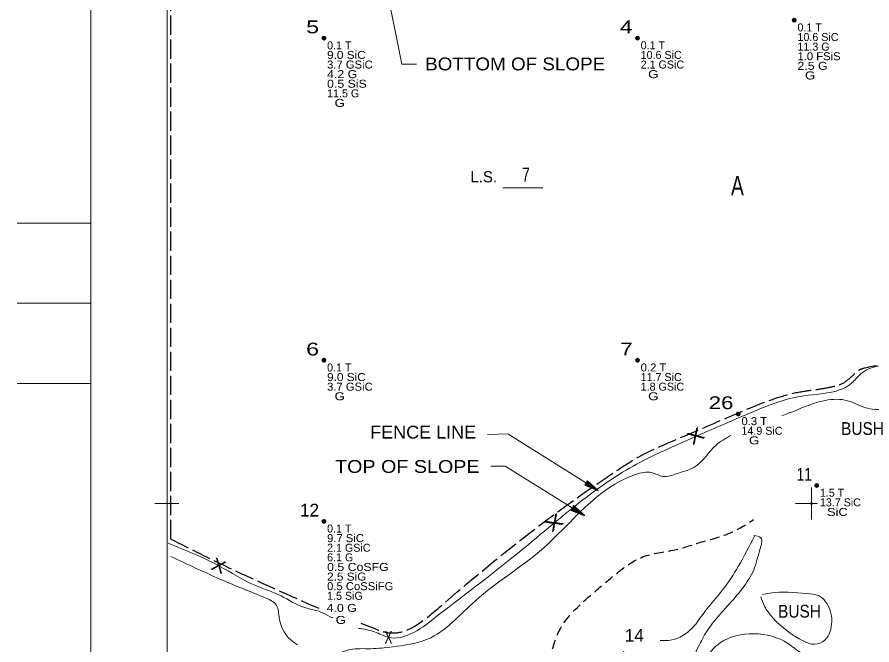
# Model space of a CAD drawing. Extents: x -496 to 480, y -450 to 700.
# Drawn here: x -496 to 38, y -88 to 304 of the extents above; entities that cross this region are included whole.
import ezdxf
from ezdxf.enums import TextEntityAlignment as Align

# ---------------------------------------------------------------- set-up
doc = ezdxf.new("R2010")
doc.units = 0
doc.header["$LTSCALE"] = 2
doc.header["$PDMODE"] = 32
doc.header["$PDSIZE"] = 1
doc.linetypes.add('LONG_DASHED', pattern=[7.5, 6, -1.5])
doc.linetypes.add('MEDIUM_DASHED', pattern=[4.5, 3, -1.5])
for name, color, linetype, lineweight in [('1', 7, 'Continuous', 13), ('2', 7, 'Continuous', 35), ('3', 7, 'Continuous', 13), ('4', 7, 'Continuous', 25)]:
    doc.layers.add(name, color=color, linetype=linetype, lineweight=lineweight)

msp = doc.modelspace()

# ---------------------------------------------------------------- linework, layer by layer
at = {"layer": '1'}
for p, q in [((-402.391, 402.339), (-402.391, -402.333)), ((-192.754, 197.096), (-167.754, 197.096)), ((-450.017, 174.973), (-496.057, 174.973)), ((-450.017, 124.973), (-496.057, 124.973)), ((-450.017, 74.973), (-496.057, 74.973)), ((-0.017, -10.027), (-0.017, 9.973)), ((-395.017, -0.027), (-410.017, -0.027)), ((-10.017, -0.027), (3.779, -0.027))]:
    msp.add_line(p, q, dxfattribs=at)
msp.add_lwpolyline([(449.983, -450.027), (449.983, 399.973), (449.983, 699.973), (-450.017, 699.973), (-450.017, 49.973), (-450.017, -450.027)], dxfattribs=at)
for p in [(0, 0), (0.001, -0.011)]:
    msp.add_point(p, dxfattribs=at)
at = {"layer": '2', "linetype": 'LONG_DASHED', "lineweight": 25}
msp.add_line((-400, -22.268), (-400, 393.12), dxfattribs=at)
at = {"layer": '2'}
for centre in [(-10.765, 301.781), (-304.484, 290.604), (-108.671, 290.604), (-304.484, 89.429), (-108.671, 89.429), (-45.731, 55.9), (3.222, 11.194), (-304.484, -11.159)]:
    msp.add_circle(centre, 1, dxfattribs=at)
for points in [[(-10.775, 302.668), (-10.045, 302.263), (-9.894, 301.415), (-10.579, 300.887), (-11.388, 301.117), (-11.674, 301.876), (-11.427, 302.437), (-10.854, 302.606), (-10.18, 302.112), (-10.197, 301.37), (-10.714, 301.112), (-11.236, 301.28), (-11.461, 301.926), (-10.877, 302.392), (-10.438, 301.859), (-10.478, 301.376), (-11.107, 301.511), (-10.961, 302.145), (-10.669, 301.595)], [(-304.495, 291.491), (-303.765, 291.087), (-303.613, 290.239), (-304.298, 289.711), (-305.107, 289.941), (-305.394, 290.699), (-305.147, 291.261), (-304.574, 291.429), (-303.9, 290.935), (-303.916, 290.194), (-304.433, 289.935), (-304.956, 290.104), (-305.18, 290.75), (-304.596, 291.216), (-304.158, 290.682), (-304.197, 290.199), (-304.826, 290.334), (-304.68, 290.969), (-304.388, 290.418)], [(-108.682, 291.491), (-107.952, 291.087), (-107.8, 290.239), (-108.485, 289.711), (-109.294, 289.941), (-109.581, 290.699), (-109.334, 291.261), (-108.761, 291.429), (-108.087, 290.935), (-108.103, 290.194), (-108.62, 289.935), (-109.143, 290.104), (-109.367, 290.75), (-108.783, 291.216), (-108.345, 290.682), (-108.384, 290.199), (-109.013, 290.334), (-108.867, 290.969), (-108.575, 290.418)], [(-304.495, 90.316), (-303.765, 89.911), (-303.613, 89.063), (-304.298, 88.535), (-305.107, 88.766), (-305.394, 89.524), (-305.147, 90.085), (-304.574, 90.254), (-303.9, 89.76), (-303.916, 89.018), (-304.433, 88.76), (-304.956, 88.928), (-305.18, 89.574), (-304.596, 90.041), (-304.158, 89.507), (-304.197, 89.024), (-304.826, 89.159), (-304.68, 89.793), (-304.388, 89.243)], [(-108.682, 90.316), (-107.952, 89.911), (-107.8, 89.063), (-108.485, 88.535), (-109.294, 88.766), (-109.581, 89.524), (-109.334, 90.085), (-108.761, 90.254), (-108.087, 89.76), (-108.103, 89.018), (-108.62, 88.76), (-109.143, 88.928), (-109.367, 89.574), (-108.783, 90.041), (-108.345, 89.507), (-108.384, 89.024), (-109.013, 89.159), (-108.867, 89.793), (-108.575, 89.243)], [(-45.742, 56.787), (-45.012, 56.382), (-44.86, 55.534), (-45.545, 55.006), (-46.354, 55.236), (-46.641, 55.995), (-46.394, 56.556), (-45.821, 56.725), (-45.147, 56.231), (-45.163, 55.489), (-45.68, 55.231), (-46.203, 55.399), (-46.427, 56.045), (-45.843, 56.511), (-45.405, 55.978), (-45.444, 55.495), (-46.073, 55.63), (-45.927, 56.264), (-45.635, 55.714)], [(3.211, 12.081), (3.941, 11.677), (4.093, 10.828), (3.408, 10.3), (2.599, 10.531), (2.312, 11.289), (2.56, 11.851), (3.133, 12.019), (3.807, 11.525), (3.79, 10.783), (3.273, 10.525), (2.751, 10.694), (2.526, 11.34), (3.11, 11.806), (3.548, 11.272), (3.509, 10.789), (2.88, 10.924), (3.026, 11.559), (3.318, 11.008)], [(-304.495, -10.272), (-303.765, -10.676), (-303.613, -11.524), (-304.298, -12.052), (-305.107, -11.822), (-305.394, -11.064), (-305.147, -10.502), (-304.574, -10.334), (-303.9, -10.828), (-303.916, -11.569), (-304.433, -11.828), (-304.956, -11.659), (-305.18, -11.013), (-304.596, -10.547), (-304.158, -11.081), (-304.197, -11.564), (-304.826, -11.429), (-304.68, -10.794), (-304.388, -11.345)]]:
    msp.add_spline(points, degree=3, dxfattribs=at)
at = {"layer": '2', "linetype": 'LONG_DASHED', "lineweight": 25}
for points in [[(-121.657, 20.504), (-107.33, 29.42), (-86.423, 39.115), (-52.45, 53.658), (-20.343, 66.337), (-7.277, 69.693), (3.177, 71.184), (11.763, 72.676), (19.23, 74.913), (25.95, 80.134), (29.31, 83.117), (33.043, 84.609), (52.83, 86.846), (92.03, 92.813), (102.856, 97.66), (117.79, 105.118), (135.71, 132.34)], [(-281.478, -74.806), (-272.712, -78.174), (-265.294, -80.532), (-255.853, -80.195), (-248.098, -76.827), (-232.251, -64.703), (-140.876, 7.369), (-121.657, 20.504)], [(-400, -22.268), (-363.749, -40.117), (-307.103, -65.713)]]:
    msp.add_spline(points, degree=3, dxfattribs=at)
at = {"layer": '3'}
for points in [[(-282.859, -78.008), (-272.887, -80.134), (-264.057, -83.662), (-249.928, -81.31), (-235.8, -71.902), (-185.173, -32.505), (-142.788, 2.187), (-109.233, 24.531), (-88.629, 34.527), (-62.138, 46.287), (-34.47, 58.047), (-7.39, 66.867), (13.803, 69.807), (24.988, 75.099), (30.874, 80.979), (65.607, 86.271), (91.509, 90.387), (107.404, 97.443), (119.177, 102.736), (137.427, 130.372)], [(-18.491, 54.826), (-14.454, 56.283), (6.738, 63.927), (20.867, 64.515), (33.818, 59.811), (45.003, 59.223), (51.478, 63.339), (58.543, 71.571)], [(-301.554, -94.191), (-299.967, -94.246), (-288.193, -91.306), (-275.242, -90.718), (-261.702, -89.542), (-239.921, -84.838), (-209.898, -60.73), (-168.69, -28.977), (-109.821, 18.063), (-99.814, 19.239), (-92.749, 16.887), (-83.919, 18.651), (-72.145, 23.355), (-59.783, 36.291), (-50.295, 42.403)], [(-36.052, -20.014), (-31.68, -21.469), (-32.166, -28.746), (-36.052, -41.359), (-52.565, -64.16), (-61.793, -74.833), (-68.107, -84.535), (-70.535, -89.387), (-71.992, -95.208), (-68.107, -97.634), (-64.221, -94.238), (-56.936, -86.961), (-14.681, -87.446), (-6.425, -93.268), (3.289, -98.604), (6.203, -105.881), (3.289, -241.716), (-9.824, -255.784), (-18.567, -261.121), (-23.909, -263.061), (-40.423, -267.912), (-54.508, -271.308), (-63.736, -281.496), (-78.792, -293.139), (-99.676, -310.118), (-116.675, -322.246), (-126.875, -337.77), (-143.388, -346.987), (-163.301, -346.017), (-177.386, -344.562), (-175.443, -326.612), (-169.13, -309.633), (-155.53, -291.198), (-125.903, -268.883), (-106.476, -244.141), (-108.419, -241.23), (-114.733, -244.141), (-133.189, -258.21), (-151.159, -275.189), (-161.359, -282.951), (-170.587, -288.773), (-178.358, -288.287), (-181.272, -279.555), (-180.786, -266.942), (-181.757, -259.18), (-187.586, -255.299), (-191.957, -255.784), (-194.385, -260.635), (-203.613, -267.427), (-209.442, -264.031), (-212.356, -260.635), (-214.784, -261.121), (-217.212, -266.457), (-220.127, -286.347), (-232.754, -288.773), (-245.382, -286.832), (-257.039, -279.07), (-275.009, -236.379), (-273.552, -227.162), (-261.896, -212.123), (-231.297, -194.173), (-183.214, -167.492), (-163.301, -158.274), (-122.504, -153.908), (-109.39, -152.453), (-100.162, -147.116), (-92.877, -142.265), (-71.021, -142.75), (-67.135, -141.78), (-64.221, -138.384), (-64.707, -134.503), (-79.278, -133.048), (-94.334, -123.345), (-104.533, -122.375), (-117.161, -121.89), (-119.59, -118.979), (-121.047, -102), (-117.209, -92.358)], [(-94.405, -85.553), (-88.991, -85.506), (-75.878, -79.199), (-66.65, -67.556), (-55.479, -53.973), (-45.765, -39.419), (-35.566, -20.499)], [(-401.809, -24.861), (-370.02, -38.973), (-347.062, -51.321), (-331.167, -57.79), (-317.039, -64.846), (-306.442, -67.786), (-300.555, -70.726), (-298.936, -71.514)], [(-400.043, -33.093), (-369.432, -47.205), (-342.352, -58.378), (-334.11, -63.67), (-332.344, -71.902), (-323.514, -86.602), (-321.029, -88.274)], [(-30.653, -56.921), (-26.027, -55.93), (-2.896, -56.26), (4.373, -57.581), (11.643, -66.822), (12.634, -73.753), (8.338, -85.305), (2.06, -87.945), (-4.879, -85.965), (-24.044, -71.443), (-29.331, -64.182), (-31.644, -58.241)]]:
    msp.add_spline(points, degree=3, dxfattribs=at)
at = {"layer": '3', "linetype": 'MEDIUM_DASHED', "lineweight": 25}
msp.add_spline([(-305.408, -229.098), (-272.087, -215.55), (-246.937, -193.569), (-226.728, -176.523), (-204.722, -159.477), (-184.063, -140.188), (-168.793, -115.965), (-162.955, -95.778), (-157.117, -78.732), (-138.255, -57.649), (-121.189, -43.294), (-105.47, -33.426), (-85.26, -28.94), (-69.991, -24.454), (-49.332, -17.725), (-36.308, -10.099)], degree=3, dxfattribs=at)
at = {"layer": '4', "lineweight": 13}
for points in [[(-246.676, 274.4), (-255.855, 274.4), (-266.346, 327.448)], [(-202.379, 43.052), (-189.598, 43.464), (-133.114, 8.048)], [(-200.318, 23.285), (-191.247, 23.285), (-141.773, -7.601)]]:
    msp.add_lwpolyline(points, dxfattribs=at)
at = {"layer": '4'}
for points in [[(-133.114, 8.048), (-139.943, 14.1), (-141.536, 11.558)], [(-141.773, -7.601), (-148.613, -1.563), (-150.201, -4.108)]]:
    msp.add_lwpolyline(points, close=True, dxfattribs=at)
for points in [[(-139.928, 13.985), (-133.479, 8.277), (-141.367, 11.597), (-139.969, 13.857), (-133.947, 8.57), (-141.176, 11.629), (-139.92, 13.694), (-134.441, 8.88), (-140.965, 11.69), (-139.923, 13.505), (-134.995, 9.246), (-140.736, 11.718), (-139.872, 13.28), (-135.66, 9.684), (-140.509, 11.806), (-139.838, 13.029), (-136.379, 10.153), (-140.202, 11.9), (-139.767, 12.776), (-137.151, 10.694), (-139.879, 11.927), (-139.665, 12.482), (-138.107, 11.275), (-139.486, 12.005)], [(-148.597, -1.677), (-142.137, -7.373), (-150.033, -4.068), (-148.638, -1.805), (-142.606, -7.08), (-149.841, -4.036), (-148.589, -1.969), (-143.101, -6.771), (-149.631, -3.975), (-148.592, -2.157), (-143.656, -6.407), (-149.401, -3.946), (-148.54, -2.382), (-144.321, -5.97), (-149.174, -3.858), (-148.506, -2.633), (-145.041, -5.503), (-148.868, -3.763), (-148.435, -2.886), (-145.814, -4.963), (-148.545, -3.735), (-148.332, -3.18), (-146.771, -4.384), (-148.152, -3.657)]]:
    msp.add_lwpolyline(points, dxfattribs=at)

# ---------------------------------------------------------------- texts
at = {"layer": '1', "width": 0.75}
msp.add_text('7', height=8.89, dxfattribs=at).set_placement((-178.356, 200.886), align=Align.CENTER)
at = {"layer": '1'}
msp.add_text('L.S.', height=7, dxfattribs=at).set_placement((-204.667, 200.511), align=Align.CENTER)
at = {"layer": '2'}
for s, width, p in [('  5', 1.35, (-307.485, 293.604)), ('  4', 1.35, (-111.672, 293.604)), ('  6', 1.35, (-307.485, 92.429)), ('  7', 1.3, (-111.672, 92.429)), (' 26', 1.3, (-48.732, 58.9)), (' 11', 0.8, (0.222, 14.194))]:
    msp.add_text(s, height=8, dxfattribs=dict(at, width=width)).set_placement(p, align=Align.RIGHT)
for s, p in [('0.1 T      ', (-8.765, 294.781)), ('10.6 SiC   ', (-8.765, 288.781)), ('0.1 T      ', (-302.484, 283.604)), ('0.1 T      ', (-106.671, 283.604)), ('11.3 G     ', (-8.765, 282.781)), ('10.6 SiC   ', (-106.671, 277.604)), ('2.1 GSiC   ', (-106.671, 271.604)), ('11.5 G     ', (-302.484, 253.604)), ('0.1 T      ', (-302.484, 82.429)), ('11.7 SiC   ', (-106.671, 76.429)), ('1.8 GSiC   ', (-106.671, 70.429)), ('14.9 SiC   ', (-43.731, 42.9)), ('1.5 T      ', (5.222, 4.194)), ('13.7 SiC   ', (5.222, -1.806)), ('0.1 T      ', (-302.484, -18.159)), ('2.1 GSiC   ', (-302.484, -30.159)), ('6.1 G      ', (-302.484, -36.159)), ('1.5 SiG    ', (-302.484, -60.159))]:
    msp.add_text(s, height=5, dxfattribs=at).set_placement(p)
for s, width, p in [('9.0 SiC    ', 1.1, (-302.484, 277.604)), ('1.0 FSiS   ', 1.05, (-8.765, 276.781)), ('3.7 GSiC   ', 1.05, (-302.484, 271.604)), ('2.5 G      ', 1.15, (-8.765, 270.781)), ('4.2 G      ', 1.15, (-302.484, 265.604)), ('  G        ', 1.25, (-106.671, 265.604)), ('  G        ', 1.25, (-8.765, 264.781)), ('0.5 SiS    ', 1.15, (-302.484, 259.604)), ('  G        ', 1.25, (-302.484, 247.604)), ('0.2 T      ', 1.05, (-106.671, 82.429)), ('9.0 SiC    ', 1.1, (-302.484, 76.429)), ('3.7 GSiC   ', 1.05, (-302.484, 70.429)), ('  G        ', 1.25, (-302.484, 64.429)), ('  G        ', 1.25, (-106.671, 64.429)), ('0.3 T      ', 1.05, (-43.731, 48.9)), ('  G        ', 1.25, (-43.731, 36.9)), ('  SiC      ', 1.2, (5.222, -7.806)), ('9.7 SiC    ', 1.05, (-302.484, -24.159)), ('0.5 CoSFG  ', 1.15, (-302.484, -42.159)), ('2.5 SiG    ', 1.1, (-302.484, -48.159)), ('0.5 CoSSiFG', 1.05, (-302.484, -54.159)), ('4.0 G      ', 1.15, (-302.763, -67.739)), ('  G        ', 1.25, (-301.825, -75.244))]:
    msp.add_text(s, height=5, dxfattribs=dict(at, width=width)).set_placement(p)
at = {"layer": '2', "width": 0.75}
msp.add_text('A', height=12, dxfattribs=at).set_placement((-46.258, 192.423), align=Align.CENTER)
at = {"layer": '2'}
for s, p in [(' 12', (-307.485, -8.159)), (' 14', (-104.678, -86.394))]:
    msp.add_text(s, height=8, dxfattribs=at).set_placement(p, align=Align.RIGHT)
at = {"layer": '3'}
for rotation, width, p in [(31.671, 1.4, (-70.276, 38.762)), (216.207, 1.55, (-162.926, -8.825)), (337.203, 1.2, (-371.683, -42.56))]:
    msp.add_text('X', height=8, rotation=rotation, dxfattribs=dict(at, width=width)).set_placement(p, align=Align.CENTER)
at = {"layer": '3', "width": 0.7}
msp.add_text('X', height=8, dxfattribs=at).set_placement((-264.168, -87.62), align=Align.CENTER)
at = {"layer": '4'}
for s, width, p in [('BOTTOM OF SLOPE', 1.1, (-185.042, 270.47)), ('FENCE LINE', 1.05, (-242.494, 40.529)), ('BUSH', 0.9, (31.849, 42.765)), ('TOP OF SLOPE', 1.15, (-252.39, 19.098)), ('BUSH', 0.9, (-7.491, -71.316))]:
    msp.add_text(s, height=8, dxfattribs=dict(at, width=width)).set_placement(p, align=Align.CENTER)

doc.saveas('drawing.dxf')
